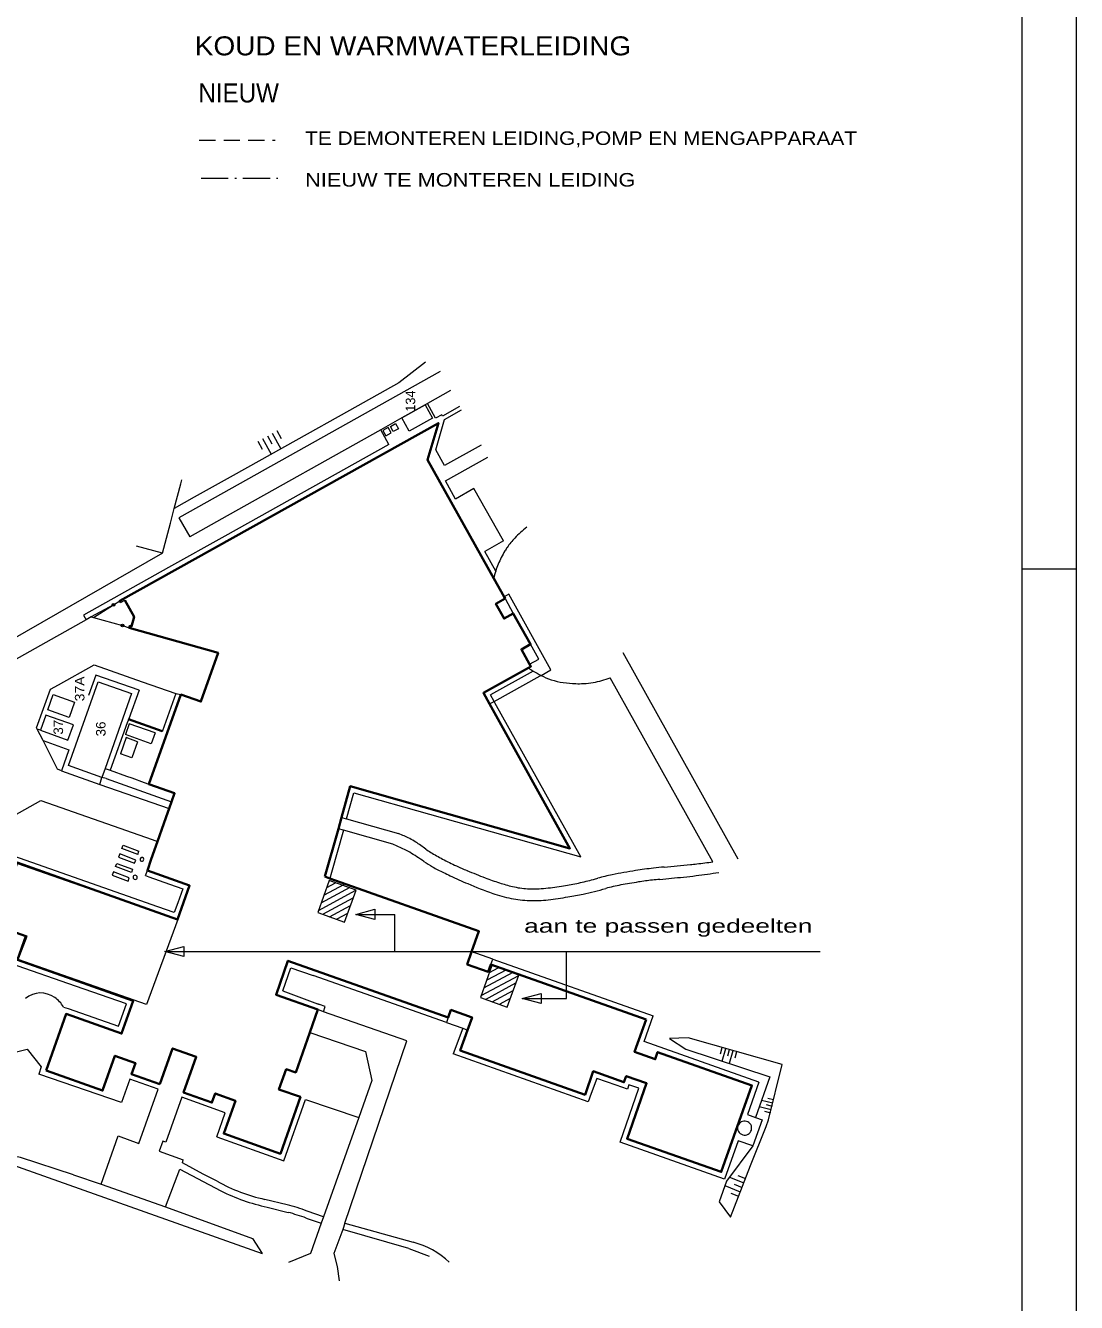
# Model space of a CAD drawing. Extents: x 295824 to 414724, y 24924 to 109024.
# Drawn here: x 395365 to 414724, y 41119 to 64629 of the extents above; entities that cross this region are included whole.
import ezdxf

# ---------------------------------------------------------------- set-up
doc = ezdxf.new("R2010")
doc.units = 0
doc.header["$LTSCALE"] = 100
doc.header["$PDMODE"] = 32
doc.header["$PDSIZE"] = 50
doc.linetypes.add('DOT_DASHED', pattern=[7.7, 5, -1.2, 0.3, -1.2])
doc.linetypes.add('MEDIUM_DASHED', pattern=[4.5, 3, -1.5])
for name, color, linetype, lineweight in [('1', 7, 'Continuous', 13), ('16', 7, 'Continuous', 13), ('19', 7, 'Continuous', 13), ('20', 7, 'Continuous', 13), ('22', 7, 'Continuous', 13), ('25', 7, 'Continuous', 13), ('26', 7, 'Continuous', 13), ('30', 7, 'Continuous', 13), ('32', 7, 'Continuous', 13), ('4', 7, 'Continuous', 35), ('40', 7, 'Continuous', 13), ('51', 7, 'Continuous', 13), ('52', 7, 'Continuous', 13), ('61', 7, 'Continuous', 13), ('62', 7, 'Continuous', 13)]:
    doc.layers.add(name, color=color, linetype=linetype, lineweight=lineweight)
doc.layers.add('57', color=7, linetype='Continuous')

msp = doc.modelspace()

# ---------------------------------------------------------------- linework, layer by layer
at = {"layer": '1'}
for p, q in [((414723.6, 24923.8), (414723.6, 109023.8)), ((413723.6, 54623.8), (414723.6, 54623.8))]:
    msp.add_line(p, q, dxfattribs=at)
msp.add_lwpolyline([(304995.6, 25923.8), (413723.6, 25923.8), (413723.6, 108023.8), (304995.6, 108023.8)], dxfattribs=at)
at = {"layer": '16'}
for p, q in [((400760.1, 48338.2), (401452.1, 48708.6)), ((400811, 48478.9), (401346.5, 48765.5)), ((400871.6, 48624.8), (401229.7, 48816.4)), ((400912.8, 48760.3), (401073.9, 48846.5)), ((400838.7, 48266.9), (401401.2, 48568)), ((400965.2, 48221.2), (401350.3, 48427.3)), ((401107.5, 48183.9), (401299.4, 48286.6)), ((401447.5, 48265), (402165.2, 48265)), ((402165.2, 47581.5), (402165.2, 48265)), ((403911, 47193.6), (404072, 47279.9)), ((403758.2, 46771.6), (404450.2, 47142)), ((403809.1, 46912.3), (404344.6, 47198.9)), ((403869.7, 47058.1), (404227.8, 47249.8)), ((403836.9, 46700.3), (404399.3, 47001.3)), ((403963.3, 46654.6), (404348.4, 46860.7)), ((404105.6, 46617.3), (404297.5, 46720))]:
    msp.add_line(p, q, dxfattribs=at)
for points in [[(400746.4, 48300.4), (401239.7, 48121.8), (401452.4, 48709.5), (400959.1, 48888.1)], [(403744.5, 46733.7), (404237.9, 46555.2), (404450.6, 47142.9), (403957.2, 47321.4)]]:
    msp.add_lwpolyline(points, close=True, dxfattribs=at)
msp.add_lwpolyline([(404512.3, 46715), (405329.9, 46715), (405329.9, 47581.5)], dxfattribs=at)
at = {"layer": '19'}
for p, q in [((397116.8, 54005.5), (397193.3, 54048.2)), ((397680.1, 51405.2), (397203.6, 51575.2)), ((397428.5, 51444), (397218.5, 51518.9)), ((397752.3, 51607.3), (397680.1, 51405.2)), ((397428.5, 51444), (397322.7, 51147.3)), ((397322.7, 51147.3), (397112.7, 51222.2)), ((406798.5, 46331.3), (403935.1, 47343.7))]:
    msp.add_line(p, q, dxfattribs=at)
for points in [[(402723.7, 57646.7), (402862.5, 57398.1), (402434.7, 57159.2), (402296.5, 57406.7)], [(402001.9, 57074.9), (402098.8, 57129), (402044.7, 57225.9), (401947.8, 57171.8)], [(402236.8, 57206), (402139.8, 57151.9), (402085.7, 57248.8), (402182.6, 57303)], [(396771, 50784.9), (396154.9, 51002.6), (396705.4, 52547.7), (397317.7, 52330.8), (396829.9, 50951.4)], [(395874, 52311.8), (396269.6, 52170.9), (396168.9, 51888.3), (395773.3, 52029.2)], [(396145.6, 51474), (396245.6, 51754.8), (395739.7, 51935), (395639.7, 51654.3)]]:
    msp.add_lwpolyline(points, close=True, dxfattribs=at)
for points in [[(397752.3, 51607.3), (397275.1, 51775.7), (397203.6, 51575.2)], [(403506.9, 46134.7), (403372.5, 45757.6), (405670.7, 44942.9)], [(406445.7, 44135), (408180, 43522.2), (408743.9, 45115.1)]]:
    msp.add_lwpolyline(points, dxfattribs=at)
at = {"layer": '20'}
msp.add_lwpolyline([(395773.3, 52029.2), (395874, 52311.8), (396269.6, 52170.9), (396168.9, 51888.3)], close=True, dxfattribs=at)
at = {"layer": '22'}
for p, q in [((396986.9, 53965.2), (397099.5, 54037.3)), ((397149.7, 53584.7), (397276, 53540)), ((397218.5, 51518.9), (397112.7, 51222.2))]:
    msp.add_line(p, q, dxfattribs=at)
msp.add_lwpolyline([(403912.5, 52137.9), (403997.6, 52185.2), (404842.3, 52654.5), (404861.7, 52665.3), (405043.8, 52766.5), (404269.8, 54159.6), (404179.6, 54109.5)], dxfattribs=at)
at = {"layer": '25'}
msp.add_line((409074.7, 45275.6), (408808.6, 44525.5), dxfattribs=at)
for points in [[(402733.1, 58433.9), (402241, 58048), (401330.8, 57539.6), (400343.1, 56988), (399188.3, 56342.9), (398474.2, 55944.1), (398105.1, 55737.9)], [(397887.2, 54913.6), (394257.4, 52833.9), (394062.2, 52535.1)], [(409303.4, 45498.8), (407573.7, 45994.5), (407227.9, 45980.1), (407525.4, 45780.4), (409074.7, 45275.6)], [(408763.7, 44003.7), (408277.1, 43351.8), (408144.9, 42971.8), (408348.1, 42691.9), (408721.9, 43640.6), (409005.4, 44359.8), (409052.7, 44479.7), (409303.4, 45498.8)]]:
    msp.add_lwpolyline(points, dxfattribs=at)
at = {"layer": '26'}
for p, q in [((399995.2, 57171.2), (400075.4, 57026.1)), ((399645.1, 56977.8), (399725.2, 56832.7)), ((399732.6, 57026.2), (399892.7, 56736.4)), ((399820.2, 57074.5), (399900.3, 56929.4)), ((399907.7, 57122.9), (400067.3, 56833.9)), ((408165.3, 45697.6), (408199, 45815.3)), ((408198.8, 45560.6), (408266.3, 45796.1)), ((408299.8, 45659.1), (408333.5, 45776.7)), ((408333.2, 45522.1), (408400.7, 45757.4)), ((408434.2, 45620.5), (408467.9, 45738.2)), ((408880.3, 44727.8), (409100.3, 44673.7)), ((408922.6, 44846.9), (409130.5, 44795.8)), ((409008.4, 44761.1), (409115.4, 44734.8)), ((409038.5, 44883.4), (409145.6, 44857)), ((408978.3, 44638.7), (409085.3, 44612.5)), ((408245, 43269.9), (408531.4, 43157.1)), ((408331.6, 43424.7), (408595.8, 43320.6)), ((408420.5, 43295.3), (408563.6, 43238.8)), ((408484.9, 43458.9), (408628.1, 43402.5)), ((408355.9, 43131.6), (408499.1, 43075.2))]:
    msp.add_line(p, q, dxfattribs=at)
at = {"layer": '30', "linetype": 'MEDIUM_DASHED'}
msp.add_line((398565.1, 62520.1), (399964.2, 62520.1), dxfattribs=at)
at = {"layer": '30', "linetype": 'DOT_DASHED'}
msp.add_line((398598.4, 61820.1), (400010.6, 61820.1), dxfattribs=at)
at = {"layer": '32'}
for p in [(397161.6, 49535.8), (397431.7, 49369.4)]:
    msp.add_line(p, (397453.5, 49428.5), dxfattribs=at)
for points in [[(397103.1, 49376.4), (397080.2, 49317.6), (397375, 49209.1), (397395.2, 49265.6)], [(397337.2, 49094.8), (397316.9, 49038.3), (397022, 49146.8), (397043.8, 49203.6)], [(396983.4, 49045.8), (396961.2, 48988), (397255.4, 48878), (397276.9, 48936.8)]]:
    msp.add_lwpolyline(points, close=True, dxfattribs=at)
msp.add_lwpolyline([(397431.7, 49369.4), (397139, 49477), (397161.6, 49535.8)], dxfattribs=at)
for centre, radius, start, end in [((397536.6, 49282.7), 62.3, 174.88401, 210.92845), ((397524.2, 49257.9), 58.2, 110.85429, 148.54529), ((397508.8, 49287.5), 45, 235.11752, 280.94338), ((397505.9, 49271.8), 40.5, 38.66887, 93.52701), ((397503.4, 49278.3), 37.6, 291.80741, 337.95407), ((397499.6, 49279.8), 41.7, 337.95407, 24.52464), ((397384.5, 48946.2), 38.6, 160.33052, 203.06541), ((397384.3, 48946.2), 38.4, 113.54211, 160.33052), ((397384.5, 48946.2), 38.6, 203.06541, 245.79546), ((397384.9, 48946), 38.6, 245.06344, 293.39196), ((397384.5, 48945.7), 39, 67.13969, 113.54211), ((397384.5, 48945.7), 39, 24.60068, 67.13969), ((397384.9, 48946), 38.6, 293.39196, 341.72546), ((397385.1, 48945.9), 38.4, 341.72546, 24.60068)]:
    msp.add_arc(centre, radius, start, end, dxfattribs=at)
at = {"layer": '4'}
msp.add_line((406804.4, 45156.4), (406445.7, 44135), dxfattribs=at)
for points in [[(400877.8, 48959.3), (401127, 49841.8), (401185.7, 50049.7), (401347.3, 50622.2), (405392.4, 49477.9), (403912.5, 52137.9), (403798.7, 52342.3), (404627.3, 52802.8), (404673.5, 52828.4), (404651.1, 52868.5), (404498.2, 53142), (404667.6, 53236.7), (404349.4, 53805.8), (404180.1, 53711.1), (404028.3, 53982.6), (404197.7, 54077.2), (404179.6, 54109.5), (403989.8, 54449.1), (402770.1, 56631), (402969.5, 57309), (397099.5, 54037.3), (397116.8, 54005.5)], [(397193.3, 54048.2), (397364.3, 53741.8), (397315.2, 53567.4), (397286, 53575.6), (397276, 53540), (398911.5, 53079.8), (398594.5, 52180.9), (398227, 52309.8), (397639.2, 50662.7)], [(395742.9, 45388.9), (396111, 46430.9), (397133.9, 46069.5), (397346.7, 46673.2), (396330.5, 47033.3), (395214.7, 47428.7), (395368.4, 47862.7), (394802.2, 48065.5), (395211.7, 49218.2), (398165.7, 48168.8), (398388.3, 48795.4), (397610, 49071.9), (397680.9, 49281.3), (397797.3, 49609.2), (397913.9, 49937.8), (397988.6, 50148.9), (398010.8, 50211.6), (398055.5, 50338.5), (398109.2, 50495), (397639.2, 50662.7)], [(400877.8, 48959.3), (400970.7, 48926.4), (403715.1, 47953.4), (403581.5, 47576.7), (403500.7, 47342.9), (403885.8, 47204.2), (403935.1, 47343.7), (406798.5, 46331.3)], [(406963.2, 45598.5), (407007.8, 45727.9), (408743.9, 45115.1), (408180, 43522.2), (406445.7, 44135), (406804.4, 45156.4), (406429, 45288.3), (406388.5, 45173.2), (405824, 45375.5), (405670.7, 44942.9), (403372.5, 45757.6), (403506.9, 46134.7), (403589.5, 46366.7), (403200.3, 46505.2), (403151.7, 46367.5), (400198.8, 47410), (399979.4, 46784.3), (400751.4, 46511.1), (400603.3, 46092.4), (400342.3, 45354.9), (400168.7, 45413.5), (400033.9, 45043.3), (400429.8, 44903.2), (400060.4, 43858.9), (399016.3, 44228.5), (399231.8, 44834.2), (398858.8, 44967), (398798.8, 44798.5), (398275.6, 44984.7), (398509.3, 45641), (398074.1, 45795.7), (397840.7, 45139.1)], [(406798.5, 46331.3), (406585.4, 45731.8), (406963.2, 45598.5), (407007.8, 45727.9), (408743.9, 45115.1)], [(397840.7, 45139.1), (397316.6, 45325.3), (397388.4, 45527.9), (397011.4, 45661.3), (396784.6, 45020.4), (395742.9, 45388.9)]]:
    msp.add_lwpolyline(points, dxfattribs=at)
at = {"layer": '4', "lineweight": 13}
for centre, start, end in [((408612, 44328.9), 29.64, 208.17622), ((408611, 44330.8), 209.13476, 28.68146)]:
    msp.add_arc(centre, 130, start, end, dxfattribs=at)
at = {"layer": '40'}
for p, q in [((397887.2, 54913.6), (397408.7, 55042.7)), ((396986.9, 53965.2), (396577.1, 53740.6)), ((396618.1, 53729.4), (396986.9, 53965.2)), ((396618.1, 53729.4), (397149.7, 53584.7)), ((397260.5, 51847.9), (397267.3, 51866.7)), ((397888.8, 51645), (397267.3, 51866.7))]:
    msp.add_line(p, q, dxfattribs=at)
for points in [[(397887.2, 54913.6), (398034.2, 55469.6), (398105.1, 55737.9), (398225.6, 56193.9), (398243.8, 56262.9)], [(396577.1, 53740.6), (396618.1, 53729.4), (397149.7, 53584.7)], [(397888.8, 51645), (397882.1, 51626.1), (397260.5, 51847.9)]]:
    msp.add_lwpolyline(points, dxfattribs=at)
for p in [(396986.9, 53965.2), (397149.7, 53584.7)]:
    msp.add_point(p, dxfattribs=at)
at = {"layer": '51'}
for p, q in [((402922.2, 56819.4), (403080.2, 57376.5)), ((403080.2, 57376.5), (403395.5, 57552.5)), ((402058.8, 56915.5), (401906.8, 57187.8)), ((403758.5, 56900.7), (403084.5, 56526.9)), ((403084.5, 56526.9), (402922.2, 56819.4)), ((404169.3, 55141.8), (403822.6, 54948)), ((404025.3, 54585.4), (403822.6, 54948)), ((404197.7, 54077.2), (404349.4, 53805.8)), ((406367.1, 53083.9), (408484.5, 49285.8)), ((404716.6, 52744), (403931.5, 52303.7)), ((408023.2, 49231.4), (406134.8, 52620.5)), ((397457.2, 52393.6), (397267.3, 51866.7)), ((398132.9, 52328.6), (397888.8, 51645)), ((395639.7, 51654.3), (395580.9, 51672.3)), ((396849.7, 50766.6), (396771, 50784.9)), ((396735.1, 50658.5), (398010.8, 50211.6)), ((396849.7, 50766.6), (398055.5, 50338.5)), ((394960.2, 49974.2), (395649.1, 50361.5)), ((401279.3, 50023.2), (401414, 50505.1)), ((401414, 50505.1), (405591.4, 49327)), ((397575.9, 48978), (397610, 49071.9)), ((400104.6, 46855.8), (400254.2, 47281.9)), ((400254.2, 47281.9), (400664.5, 47137.5)), ((403971.2, 47438.4), (406924.4, 46396.3)), ((403121.6, 46272.1), (400664.5, 47137.5)), ((397079.3, 46209.3), (397221.9, 46619.2)), ((403417.8, 46166.5), (403243.9, 45698.6)), ((401246, 42578.7), (402388.6, 45937.6)), ((405888.8, 45243.9), (405783.9, 44966.1)), ((406243.7, 45118.5), (405888.8, 45243.9)), ((398888.6, 44168.3), (399039.3, 44610.5)), ((394633.6, 43829.8), (399722.4, 42020.1)), ((397829, 43902.8), (398271.6, 43743.7)), ((397945.3, 42877.1), (398207.2, 43573.7)), ((398207.2, 43573.7), (398959.5, 43175.6)), ((400185.8, 42915.8), (399773.1, 43017.6)), ((399815.6, 42874.3), (400201.2, 42778.2)), ((401246, 42578.7), (402503.8, 42227.5)), ((399544.7, 42295.5), (399722.4, 42020.1)), ((402427.8, 42112.5), (402798.9, 41974.1))]:
    msp.add_line(p, q, dxfattribs=at)
for points in [[(403000.5, 58261.8), (398189.2, 55565.7), (398392.1, 55213.6)], [(403195.5, 57911.7), (402767.3, 57671.2), (402723.7, 57646.7), (402296.5, 57406.7), (401906.8, 57187.8), (399080.5, 55600.3), (398392.1, 55213.6)], [(403360.4, 57615.4), (403045.5, 57439.6), (403032.3, 57463.2), (402918.8, 57399.8), (402767.3, 57671.2)], [(402058.8, 56915.5), (399037.4, 55228.8), (398001.6, 54650.6), (396431.8, 53774.2), (396481.7, 53687.2)], [(404169.3, 55141.8), (403624.4, 56105.8), (403283.3, 55912), (403100.1, 56245), (403881.3, 56680.1)], [(396577.1, 53740.6), (396481.7, 53687.2), (394302.2, 52468.8)], [(404651.1, 52868.5), (404820.8, 52962.6), (404667.6, 53236.7)], [(395580.9, 51672.3), (395567.8, 51700.8), (395824.2, 52411), (395972.7, 52493.8), (396627, 52858.8), (397512.3, 52547.1), (398132.9, 52328.6), (398227, 52309.8)], [(397457.2, 52393.6), (396660.5, 52671.1), (396525.7, 52295.4)], [(405591.4, 49327), (404011.9, 52159.6), (403997.6, 52185.2), (403931.5, 52303.7)], [(397260.5, 51847.9), (397239.1, 51788.5), (396925.1, 50917.5)], [(395687, 51463.7), (396161.3, 51293), (396025.2, 50910.2), (395956, 50935.1), (395687, 51463.7), (395580.9, 51672.3)], [(396025.2, 50910.2), (396735.1, 50658.5), (396771, 50784.9)], [(396829.9, 50951.4), (396925.1, 50917.5), (397226, 50809.9), (397320.3, 50776.5)], [(397320.3, 50776.5), (397549.5, 50694.7), (397639.2, 50662.7)], [(395649.1, 50361.5), (397698.8, 49643.7), (397797.3, 49609.2)], [(402131, 49554.9), (401219.5, 49815.3), (401127, 49841.8)], [(401185.7, 50049.7), (401279.3, 50023.2), (402235.6, 49752.5)], [(401219.5, 49815.3), (401000.7, 49033.5), (400970.7, 48926.4)], [(398104.9, 48296.3), (397804.6, 48402.3), (397470.2, 48520.3), (395151.5, 49338.3)], [(397575.9, 48978), (397633.6, 48957.5), (398014.6, 48822), (398260.6, 48734.6)], [(398260.6, 48734.6), (398168.7, 48475.8), (398104.9, 48296.3)], [(403935.1, 47343.7), (403971.2, 47438.4), (403675.8, 47544.4), (403581.5, 47576.7)], [(397221.9, 46619.2), (396287.4, 46944.3), (395089.9, 47360.9)], [(400104.6, 46855.8), (400744.5, 46618.9), (400781.6, 46605.1)], [(396062.4, 46559.2), (396149.1, 46529.4), (397079.3, 46209.3)], [(402388.6, 45937.6), (400852.4, 46471.8), (400881.7, 46568), (400781.6, 46605.1), (400744.5, 46618.9)], [(403151.7, 46367.5), (403121.6, 46272.1), (403417.8, 46166.5), (403506.9, 46134.7)], [(408874.8, 45176.2), (406757.6, 45925.2), (406924.4, 46396.3)], [(394477.9, 45205.6), (395100.5, 45712.1), (395394.5, 45782.8), (395653.7, 45459.6), (395607.3, 45321.3)], [(405783.9, 44966.1), (405727.1, 44815.8), (403243.9, 45698.6)], [(396246.5, 43468.9), (396759.5, 43295.1), (397069.8, 44188.4), (397450.4, 44047.5), (397809.5, 45049), (397287.2, 45232.4), (397129.9, 44798.7), (395607.3, 45321.3)], [(408874.8, 45176.2), (408663.6, 44581.7), (408808.6, 44525.5)], [(406316.4, 44070.6), (406660.4, 45062.4), (406477.1, 45126.5), (406455.4, 45045.3), (406243.7, 45118.5)], [(399039.3, 44610.5), (398245, 44897.3), (397949.7, 44070.5), (397895.8, 44091.6), (397829, 43902.8)], [(398888.6, 44168.3), (400125.7, 43726.6), (400521.7, 44856.3), (401502.6, 44523.1), (400853.8, 42697.9), (400550, 42802.4)], [(408808.6, 44525.5), (408932.9, 44481), (408763.7, 44003.7), (408491.5, 44093.6), (408242.3, 43390.6), (406316.4, 44070.6)], [(396246.5, 43468.9), (395270.4, 43788.4), (394607.8, 43912.5)], [(398897.2, 43349.9), (398639.5, 43481.7), (398257, 43688), (398271.6, 43743.7)], [(396759.5, 43295.1), (397945.3, 42877.1), (399544.7, 42295.5)], [(400536.2, 42671.8), (400811.4, 42576.4), (400615.1, 42022.3), (400209.5, 41853.8)], [(402427.8, 42112.5), (401207.8, 42461.1), (401046.9, 42017.9), (401105.6, 41784.2), (401144.3, 41516.5)]]:
    msp.add_lwpolyline(points, dxfattribs=at)
for centre, radius, start, end in [((405533.1, 54119.4), 1578.2, 126.29056, 137.1502), ((405546.1, 54140.5), 1578, 146.04811, 148.90934), ((405528.5, 54113.1), 1579, 136.86919, 144.86761), ((405536.1, 54125.2), 1577.5, 148.248, 158.08467), ((405533.1, 54119.4), 1578.2, 162.82504, 167.93957), ((405528.1, 54105.5), 1577.5, 157.31277, 162.2913), ((405549.8, 54107.1), 1597.5, 234.73007, 238.56524), ((405549.8, 54107.1), 1597.5, 238.56524, 244.48705), ((405593.4, 54091.7), 1603.2, 242.84296, 249.97212), ((405521, 54111.3), 1598.5, 252.65339, 269.25839), ((405562.9, 54107.8), 1596.1, 267.75368, 272.9189), ((405562.9, 54107.8), 1596.1, 272.9189, 279.38393), ((405549.8, 54107.1), 1597.5, 279.85146, 291.48171), ((401087.3, 46915.9), 3060.2, 63.73678, 67.96053), ((402000.7, 48767), 996, 56.32959, 63.73678), ((400413.8, 45370.1), 4523.4, 64.74941, 67.69024), ((401903.3, 48528), 1031.8, 58.58977, 64.74941), ((399201.7, 44103.9), 6215.6, 55.7123, 58.58977), ((399655.7, 45246.9), 5225.7, 53.87718, 56.32959), ((403499, 50513), 1293.7, 233.87718, 238.80723), ((405007.2, 53004), 4205.8, 238.80723, 242.2048), ((403994.4, 51133), 2291.9, 235.7123, 240.45176), ((404447.6, 51932.4), 3210.9, 240.45176, 244.44182), ((405603.4, 54135), 5484.2, 242.2048, 245.18002), ((405501, 53913.7), 5240.4, 245.18002, 247.51654), ((408312.3, 36571.3), 12619.6, 95.37354, 96.27081), ((400073.3, 124162), 75357.8, 275.37354, 275.74072), ((406960.1, 55657.9), 6508.4, 275.74072, 276.81483), ((403278.5, 86464.9), 37534.6, 276.81483, 277.26209), ((409787.6, 63098.9), 15588.6, 244.44183, 244.94759), ((409787.6, 63098.9), 15588.6, 244.94759, 246.25241), ((409231.1, 62926.4), 14994.5, 247.51654, 248.89777), ((405472.8, 53187.6), 4555.8, 248.89777, 252.38967), ((404184.9, 55089.4), 6395.7, 282.34377, 284.86156), ((404184.9, 55089.4), 6395.7, 284.86156, 285.60827), ((406880.8, 45439), 3624.2, 101.27121, 105.60827), ((408432.1, 37655.4), 11561, 99.10473, 101.27121), ((407671.9, 42398.6), 6757.2, 96.27081, 99.10473), ((407724.2, 41711.5), 7229.3, 95.37081, 96.45394), ((400034.2, 123508.5), 74928.4, 275.37081, 275.70725), ((406682.2, 56989.2), 8077.7, 275.70725, 277.36407), ((404376.5, 74829.6), 26066.5, 277.36407, 278.28636), ((405766.4, 53959), 5603.1, 246.25241, 251.30735), ((405222.7, 52399.7), 3729.1, 252.38968, 256.2494), ((404684.9, 50201.9), 1466.4, 256.2494, 267.13568), ((404720.4, 50911.5), 2176.9, 267.13568, 276.06602), ((404261.9, 55226), 6515.7, 276.06602, 278.95687), ((404537.2, 53479.1), 4747.3, 278.95687, 282.34377), ((404069.3, 55907.1), 7435.1, 282.17071, 285.46087), ((406942.3, 45520), 3342, 100.55259, 105.46087), ((408253.8, 38480.1), 10503, 98.75261, 100.55259), ((407635.6, 42495.3), 6440.6, 96.45394, 98.75261), ((404884.6, 51352.7), 2851.8, 251.30735, 258.39517), ((404720.5, 50553.4), 2035.8, 258.39517, 267.88214), ((404725.9, 50700.8), 2183.2, 267.88214, 277.04242), ((403841.8, 57857.7), 9394.5, 277.04242, 279.28211), ((404446.1, 54160.4), 5648.3, 279.28211, 282.17072), ((395642.3, 46382.8), 435.4, 53.34093, 129.55669), ((395630.8, 46320.3), 493.3, 28.9771, 56.61769), ((400473.9, 46184.6), 3243.7, 240.91681, 257.52249), ((400584.7, 46426.7), 3634.7, 243.43983, 257.7842), ((399643.3, 40533.7), 2443.2, 68.21629, 77.1705), ((399232.2, 39145.2), 3760, 69.70629, 75.06476), ((402112, 40719.6), 1558, 47.15378, 75.43561)]:
    msp.add_arc(centre, radius, start, end, dxfattribs=at)
at = {"layer": '52'}
for p, q in [((400852.4, 46471.8), (400751.4, 46511.1)), ((400853.8, 42697.9), (400811.4, 42576.4)), ((401246, 42578.7), (401207.8, 42461.1))]:
    msp.add_line(p, q, dxfattribs=at)
msp.add_lwpolyline([(400603.3, 46092.4), (401624.6, 45739.6), (401746.4, 45206.9), (401502.6, 44523.1)], dxfattribs=at)
at = {"layer": '61'}
msp.add_line((397964.7, 47581.5), (410002, 47581.5), dxfattribs=at)
at = {"layer": '62'}
for points in [[(394813.4, 48065.7), (395216.4, 49202.6), (398171, 48171.1), (397591.6, 46603.2), (395228.2, 47433.2), (395392.8, 47861.5)], [(401447.5, 48265), (401796.5, 48358.5), (401796.5, 48171.5)], [(397933.1, 47581.7), (398282, 47675.2), (398282, 47488.2)], [(404512.3, 46715), (404861.3, 46808.5), (404861.3, 46621.5)]]:
    msp.add_lwpolyline(points, close=True, dxfattribs=at)

# ---------------------------------------------------------------- texts
at = {"layer": '16'}
for s, width, p in [('TE DEMONTEREN LEIDING,POMP EN MENGAPPARAAT', 1.15, (400514.6, 62430.4)), ('NIEUW TE MONTEREN LEIDING', 1.2, (400514.6, 61663.7))]:
    msp.add_text(s, height=250, dxfattribs=dict(at, width=width)).set_placement(p)
at = {"layer": '57'}
msp.add_text('134', height=175, rotation=90, dxfattribs=at).set_placement((402542.6, 57519.4))
for s, width, p in [('37A', 1.1, (396449.9, 52187.1)), ('37', 1.05, (396056.2, 51573.6)), ('36', 1.05, (396838.5, 51541.8))]:
    msp.add_text(s, height=175, rotation=90, dxfattribs=dict(at, width=width)).set_placement(p)
at = {"layer": '61'}
for s, height, width, p in [('KOUD EN WARMWATERLEIDING', 350, 1.1, (398483.5, 64079.9)), ('NIEUW', 350, 0.95, (398550.2, 63213.2)), ('aan te passen gedeelten', 250, 1.45, (404549.2, 47927.8))]:
    msp.add_text(s, height=height, dxfattribs=dict(at, width=width)).set_placement(p)

doc.saveas('drawing.dxf')
